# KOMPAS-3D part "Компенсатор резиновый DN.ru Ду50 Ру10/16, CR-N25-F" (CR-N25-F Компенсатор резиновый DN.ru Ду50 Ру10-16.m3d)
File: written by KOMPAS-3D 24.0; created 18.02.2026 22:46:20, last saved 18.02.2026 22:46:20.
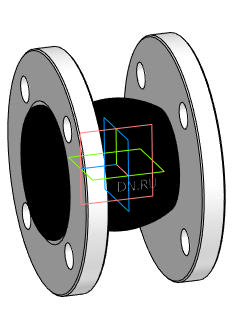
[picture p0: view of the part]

Document properties: Автор: DN.RU; Полное имя файла: D:\PROJECT CAD\DN.RU\...178(1)(ACTUALE). CR-N25-F Компенсатор резиновый DN.ru Ру10-16\DN50\CR-N25-F Компенсатор резиновый DN.ru Ду50 Ру10-16.m3d

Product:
- Body: Твердое тело2  | qty 1
    Масса: 6.569601
- Part/product: Компенсатор резиновый DN.ru Ду50 Ру10/16  | designation CR-N25-F
    Масса: 5
    Раздел спецификации: Прочие изделия
    Комментарий: D140-02391
    Примечание: D140-02391
    additional columns: Типовые

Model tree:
1. Твердое тело2  (labels: Твердое тело2)

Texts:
  CR-N25-F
